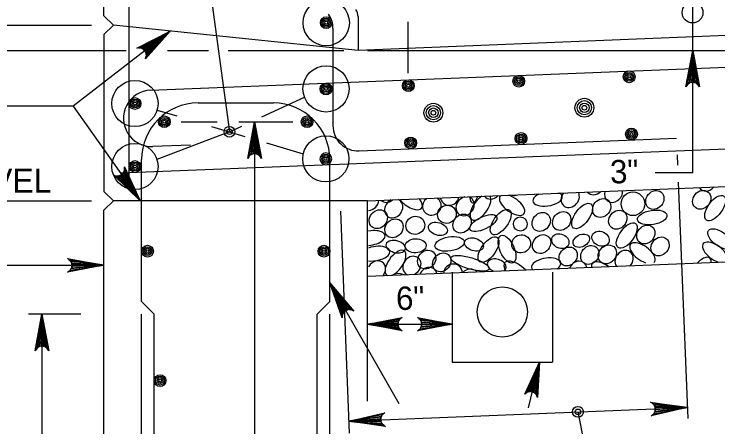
# Model space of a CAD drawing. Extents: x 638167 to 640248, y 296544 to 298920.
# Drawn here: x 639551.3 to 639646.3, y 298721.8 to 298777.5 of the extents above; entities that cross this region are included whole.
import ezdxf

# ---------------------------------------------------------------- set-up
doc = ezdxf.new("R2010")
doc.units = 0
for name, color, linetype in [('1', 7, 'Continuous'), ('50', 7, 'Continuous'), ('57', 7, 'Continuous')]:
    doc.layers.add(name, color=color, linetype=linetype)

# ---------------------------------------------------------------- blocks, each defined once
blk = doc.blocks.new('DIMDOT')
at = {"layer": '57'}
for radius in [2, 1]:
    blk.add_circle((0, 0), radius, dxfattribs=at)
blk = doc.blocks.new('BAR')
at = {"layer": '50'}
for radius in [2, 1.5, 1, 0.5]:
    blk.add_circle((0, 0), radius, dxfattribs=at)

msp = doc.modelspace()

# ---------------------------------------------------------------- linework, layer by layer
at = {"layer": '1'}
for p, q in [((639642.927, 298756.115), (639642.927, 298843.716)), ((639563.476, 298777.252), (639563.476, 298842.446)), ((639566.863, 298754.839), (639566.863, 298793.251)), ((639576.379, 298790.972), (639580.411, 298761.612)), ((639792.111, 298780.369), (639597.766, 298772.596)), ((639563.476, 298777.252), (639564.746, 298775.982)), ((639597.766, 298777.144), (639597.766, 298772.596)), ((639604.54, 298769.508), (639604.54, 298776.442)), ((639494.683, 298775.982), (639561.795, 298775.982)), ((639563.476, 298774.712), (639564.746, 298775.982)), ((639597.766, 298772.596), (639564.746, 298775.982)), ((639594.38, 298775.549), (639594.38, 298762.427)), ((639572.395, 298775.198), (639559.324, 298765.07)), ((639563.476, 298774.712), (639563.476, 298753.58)), ((639569.769, 298767.239), (639757.112, 298774.733)), ((639500.606, 298772.596), (639566.491, 298772.596)), ((639572.037, 298772.596), (639577.584, 298772.596)), ((639580.232, 298772.596), (639595.848, 298772.596)), ((639599.028, 298772.596), (639657.756, 298772.596)), ((639584.794, 298763.647), (639590.514, 298766.303)), ((639559.324, 298765.07), (639526.988, 298765.07)), ((639559.324, 298765.07), (639568.341, 298752.31)), ((639576.176, 298765.496), (639586.334, 298765.496)), ((639570.649, 298764.544), (639573.311, 298763.744)), ((639565.771, 298756.064), (639757.552, 298763.735)), ((639573.907, 298762.964), (639578.756, 298762.964)), ((639581.684, 298762.964), (639588.943, 298762.964)), ((639583.796, 298762.964), (639583.796, 298658.271)), ((639577.973, 298762.344), (639582.464, 298760.995)), ((639580.411, 298761.612), (639582.067, 298762.38)), ((639580.411, 298761.612), (639570.625, 298757.891)), ((639585.403, 298760.113), (639590.367, 298758.622)), ((639597.902, 298759.043), (639640.737, 298760.757)), ((639575.149, 298759.828), (639570.073, 298759.625)), ((639599.034, 298752.31), (639792.923, 298760.066)), ((639640.827, 298758.506), (639640.883, 298757.124)), ((639568.556, 298738.713), (639568.556, 298757.876)), ((639593.954, 298738.713), (639593.954, 298757.876)), ((639637.869, 298756.115), (639642.927, 298756.115)), ((639640.974, 298754.835), (639642.25, 298722.941)), ((639563.476, 298753.58), (639564.746, 298752.31)), ((639538.025, 298752.31), (639561.795, 298752.31)), ((639564.746, 298752.31), (639563.476, 298751.04)), ((639599.034, 298752.31), (639564.746, 298752.31)), ((639599.034, 298725.289), (639599.034, 298752.31)), ((639563.476, 298650.659), (639563.476, 298751.04)), ((639595.375, 298750.89), (639596.571, 298720.998)), ((639599.034, 298742.142), (639793.329, 298749.914)), ((639522.836, 298743.612), (639563.476, 298743.612)), ((639610.464, 298742.701), (639610.464, 298730.555)), ((639623.997, 298742.701), (639623.997, 298730.555)), ((639593.954, 298741.256), (639603.278, 298724.969)), ((639570.25, 298737.019), (639568.556, 298738.713)), ((639592.261, 298737.019), (639593.954, 298738.713)), ((639560.343, 298737.019), (639553.302, 298737.019)), ((639555.101, 298737.019), (639555.101, 298686.219)), ((639568.556, 298663.359), (639568.556, 298737.019)), ((639570.25, 298686.219), (639570.25, 298737.019)), ((639592.261, 298686.219), (639592.261, 298737.019)), ((639593.954, 298663.359), (639593.954, 298737.019)), ((639599.034, 298735.675), (639610.464, 298735.675)), ((639610.464, 298730.555), (639623.997, 298730.555)), ((639620.755, 298724.374), (639622.255, 298730.555)), ((639596.506, 298722.616), (639642.19, 298724.443)), ((639627.44, 298723.853), (639628.333, 298719.377))]:
    msp.add_line(p, q, dxfattribs=at)
for points in [[(639572.395, 298775.198), (639569.062, 298771.446), (639569.132, 298771.666), (639569.201, 298771.886), (639569.178, 298772.077), (639569.154, 298772.268), (639569.075, 298772.416), (639568.996, 298772.564), (639568.872, 298772.678), (639568.749, 298772.791), (639568.57, 298772.862), (639568.391, 298772.932), (639568.16, 298772.92), (639567.929, 298772.908), (639572.395, 298775.198), (639568.16, 298772.92), (639568.391, 298772.932), (639572.395, 298775.198), (639568.57, 298772.862), (639568.749, 298772.791), (639572.395, 298775.198), (639568.872, 298772.678), (639568.996, 298772.564), (639572.395, 298775.198), (639569.075, 298772.416), (639569.154, 298772.268), (639572.395, 298775.198), (639569.178, 298772.077), (639569.201, 298771.886), (639572.395, 298775.198), (639569.132, 298771.666)], [(639642.927, 298772.596), (639643.852, 298767.663), (639643.72, 298767.853), (639643.588, 298768.043), (639643.423, 298768.141), (639643.258, 298768.239), (639643.092, 298768.267), (639642.927, 298768.296), (639642.761, 298768.267), (639642.596, 298768.239), (639642.431, 298768.141), (639642.265, 298768.043), (639642.134, 298767.853), (639642.002, 298767.663), (639642.927, 298772.596), (639642.134, 298767.853), (639642.265, 298768.043), (639642.927, 298772.596), (639642.431, 298768.141), (639642.596, 298768.239), (639642.927, 298772.596), (639642.761, 298768.267), (639642.927, 298768.296), (639642.927, 298772.596), (639643.092, 298768.267), (639643.258, 298768.239), (639642.927, 298772.596), (639643.423, 298768.141), (639643.588, 298768.043), (639642.927, 298772.596), (639643.72, 298767.853)], [(639583.796, 298762.964), (639584.721, 298758.031), (639584.59, 298758.221), (639584.458, 298758.411), (639584.293, 298758.509), (639584.127, 298758.607), (639583.962, 298758.635), (639583.796, 298758.664), (639583.631, 298758.635), (639583.466, 298758.607), (639583.3, 298758.509), (639583.135, 298758.411), (639583.003, 298758.221), (639582.872, 298758.031), (639583.796, 298762.964), (639583.003, 298758.221), (639583.135, 298758.411), (639583.796, 298762.964), (639583.3, 298758.509), (639583.466, 298758.607), (639583.796, 298762.964), (639583.631, 298758.635), (639583.796, 298758.664), (639583.796, 298762.964), (639583.962, 298758.635), (639584.127, 298758.607), (639583.796, 298762.964), (639584.293, 298758.509), (639584.458, 298758.411), (639583.796, 298762.964), (639584.59, 298758.221)], [(639568.341, 298752.31), (639564.739, 298755.805), (639564.956, 298755.725), (639565.173, 298755.646), (639565.365, 298755.662), (639565.557, 298755.677), (639565.708, 298755.749), (639565.859, 298755.822), (639565.978, 298755.94), (639566.097, 298756.059), (639566.175, 298756.234), (639566.254, 298756.41), (639566.252, 298756.641), (639566.25, 298756.872), (639568.341, 298752.31), (639566.252, 298756.641), (639566.254, 298756.41), (639568.341, 298752.31), (639566.175, 298756.234), (639566.097, 298756.059), (639568.341, 298752.31), (639565.978, 298755.94), (639565.859, 298755.822), (639568.341, 298752.31), (639565.708, 298755.749), (639565.557, 298755.677), (639568.341, 298752.31), (639565.365, 298755.662), (639565.173, 298755.646), (639568.341, 298752.31), (639564.956, 298755.725)], [(639563.476, 298743.612), (639558.544, 298742.687), (639558.734, 298742.819), (639558.924, 298742.951), (639559.022, 298743.116), (639559.12, 298743.281), (639559.148, 298743.447), (639559.177, 298743.612), (639559.148, 298743.778), (639559.12, 298743.943), (639559.022, 298744.108), (639558.924, 298744.274), (639558.734, 298744.405), (639558.544, 298744.537), (639563.476, 298743.612), (639558.734, 298744.405), (639558.924, 298744.274), (639563.476, 298743.612), (639559.022, 298744.108), (639559.12, 298743.943), (639563.476, 298743.612), (639559.148, 298743.778), (639559.177, 298743.612), (639563.476, 298743.612), (639559.148, 298743.447), (639559.12, 298743.281), (639563.476, 298743.612), (639559.022, 298743.116), (639558.924, 298742.951), (639563.476, 298743.612), (639558.734, 298742.819)], [(639593.954, 298741.256), (639597.207, 298737.434), (639596.998, 298737.534), (639596.79, 298737.633), (639596.598, 298737.636), (639596.405, 298737.639), (639596.248, 298737.582), (639596.09, 298737.524), (639595.961, 298737.417), (639595.831, 298737.31), (639595.736, 298737.143), (639595.642, 298736.976), (639595.622, 298736.746), (639595.602, 298736.515), (639593.954, 298741.256), (639595.622, 298736.746), (639595.642, 298736.976), (639593.954, 298741.256), (639595.736, 298737.143), (639595.831, 298737.31), (639593.954, 298741.256), (639595.961, 298737.417), (639596.09, 298737.524), (639593.954, 298741.256), (639596.248, 298737.582), (639596.405, 298737.639), (639593.954, 298741.256), (639596.598, 298737.636), (639596.79, 298737.633), (639593.954, 298741.256), (639596.998, 298737.534)], [(639555.101, 298737.019), (639556.026, 298732.087), (639555.895, 298732.277), (639555.763, 298732.467), (639555.598, 298732.565), (639555.432, 298732.663), (639555.267, 298732.691), (639555.101, 298732.72), (639554.936, 298732.691), (639554.771, 298732.663), (639554.605, 298732.565), (639554.44, 298732.467), (639554.308, 298732.277), (639554.177, 298732.087), (639555.101, 298737.019), (639554.308, 298732.277), (639554.44, 298732.467), (639555.101, 298737.019), (639554.605, 298732.565), (639554.771, 298732.663), (639555.101, 298737.019), (639554.936, 298732.691), (639555.101, 298732.72), (639555.101, 298737.019), (639555.267, 298732.691), (639555.432, 298732.663), (639555.101, 298737.019), (639555.598, 298732.565), (639555.763, 298732.467), (639555.101, 298737.019), (639555.895, 298732.277)], [(639599.034, 298735.675), (639603.732, 298736.556), (639603.551, 298736.431), (639603.37, 298736.305), (639603.276, 298736.148), (639603.183, 298735.99), (639603.156, 298735.833), (639603.129, 298735.675), (639603.156, 298735.518), (639603.183, 298735.36), (639603.276, 298735.203), (639603.37, 298735.045), (639603.551, 298734.92), (639603.732, 298734.794), (639599.034, 298735.675), (639603.551, 298734.92), (639603.37, 298735.045), (639599.034, 298735.675), (639603.276, 298735.203), (639603.183, 298735.36), (639599.034, 298735.675), (639603.156, 298735.518), (639603.129, 298735.675), (639599.034, 298735.675), (639603.156, 298735.833), (639603.183, 298735.99), (639599.034, 298735.675), (639603.276, 298736.148), (639603.37, 298736.305), (639599.034, 298735.675), (639603.551, 298736.431)], [(639610.464, 298735.675), (639605.766, 298734.794), (639605.947, 298734.92), (639606.128, 298735.045), (639606.222, 298735.203), (639606.315, 298735.36), (639606.342, 298735.518), (639606.369, 298735.675), (639606.342, 298735.833), (639606.315, 298735.99), (639606.222, 298736.148), (639606.128, 298736.305), (639605.947, 298736.431), (639605.766, 298736.556), (639610.464, 298735.675), (639605.947, 298736.431), (639606.128, 298736.305), (639610.464, 298735.675), (639606.222, 298736.148), (639606.315, 298735.99), (639610.464, 298735.675), (639606.342, 298735.833), (639606.369, 298735.675), (639610.464, 298735.675), (639606.342, 298735.518), (639606.315, 298735.36), (639610.464, 298735.675), (639606.222, 298735.203), (639606.128, 298735.045), (639610.464, 298735.675), (639605.947, 298734.92)], [(639622.255, 298730.555), (639621.965, 298725.784), (639621.887, 298725.99), (639621.81, 298726.196), (639621.68, 298726.325), (639621.55, 298726.454), (639621.404, 298726.519), (639621.257, 298726.583), (639621.098, 298726.595), (639620.939, 298726.608), (639620.763, 298726.555), (639620.588, 298726.503), (639620.422, 298726.358), (639620.256, 298726.213), (639622.255, 298730.555), (639620.422, 298726.358), (639620.588, 298726.503), (639622.255, 298730.555), (639620.763, 298726.555), (639620.939, 298726.608), (639622.255, 298730.555), (639621.098, 298726.595), (639621.257, 298726.583), (639622.255, 298730.555), (639621.404, 298726.519), (639621.55, 298726.454), (639622.255, 298730.555), (639621.68, 298726.325), (639621.81, 298726.196), (639622.255, 298730.555), (639621.887, 298725.99)], [(639642.19, 298724.443), (639637.298, 298723.322), (639637.483, 298723.461), (639637.667, 298723.6), (639637.759, 298723.769), (639637.85, 298723.938), (639637.872, 298724.105), (639637.894, 298724.271), (639637.859, 298724.435), (639637.824, 298724.599), (639637.719, 298724.761), (639637.615, 298724.922), (639637.419, 298725.046), (639637.224, 298725.17), (639642.19, 298724.443), (639637.419, 298725.046), (639637.615, 298724.922), (639642.19, 298724.443), (639637.719, 298724.761), (639637.824, 298724.599), (639642.19, 298724.443), (639637.859, 298724.435), (639637.894, 298724.271), (639642.19, 298724.443), (639637.872, 298724.105), (639637.85, 298723.938), (639642.19, 298724.443), (639637.759, 298723.769), (639637.667, 298723.6), (639642.19, 298724.443), (639637.483, 298723.461)], [(639596.506, 298722.616), (639601.398, 298723.737), (639601.213, 298723.598), (639601.029, 298723.459), (639600.937, 298723.289), (639600.846, 298723.12), (639600.824, 298722.954), (639600.803, 298722.788), (639600.838, 298722.623), (639600.873, 298722.459), (639600.977, 298722.298), (639601.082, 298722.137), (639601.277, 298722.013), (639601.472, 298721.889), (639596.506, 298722.616), (639601.277, 298722.013), (639601.082, 298722.137), (639596.506, 298722.616), (639600.977, 298722.298), (639600.873, 298722.459), (639596.506, 298722.616), (639600.838, 298722.623), (639600.803, 298722.788), (639596.506, 298722.616), (639600.824, 298722.954), (639600.846, 298723.12), (639596.506, 298722.616), (639600.937, 298723.289), (639601.029, 298723.459), (639596.506, 298722.616), (639601.213, 298723.598)]]:
    msp.add_lwpolyline(points, dxfattribs=at)
for centre, radius in [((639593.467, 298776.326), 3.119), ((639642.901, 298777.689), 1.404), ((639593.438, 298767.391), 3.119), ((639567.656, 298765.424), 3.119), ((639593.417, 298757.964), 3.119), ((639567.656, 298756.933), 3.119), ((639634.861, 298751.909), 1.595), ((639617.23, 298737.321), 3.383)]:
    msp.add_circle(centre, radius, dxfattribs=at)
for centre, radius, start, end in [((639590.993, 298775.549), 3.387, 360, 34.85446), ((639596.073, 298777.144), 1.693, 0, 34.85446), ((639569.921, 298763.432), 3.81, 92.29061, 272.29061), ((639576.176, 298757.876), 7.62, 90, 180), ((639586.334, 298757.876), 7.62, 0, 90), ((639597.766, 298762.427), 3.387, 180, 272.29061)]:
    msp.add_arc(centre, radius, start, end, dxfattribs=at)
for centre, major_axis, ratio, start_param, end_param in [((639629.72, 298754.393), (0.86, 1.048), 0.844245, 2.967408, 4.603431), ((639632.24, 298753.367), (0.86, 1.048), 0.844245, 2.008108, 5.562731), ((639644.894, 298754.888), (0.86, 1.048), 0.844245, 2.840874, 4.729965), ((639604.734, 298752.513), (-1.624, 1.174), 0.479042, 1.014341, 4.173787), ((639607.722, 298751.6), (-1.167, -0.522), 0.948581, 4.858014, 10.05193), ((639610.116, 298752.933), (-1.167, -0.522), 0.948581, 6.041055, 8.868889), ((639612.209, 298751.575), (0.86, 1.048), 0.844245, 0.812597, 6.758242), ((639614.282, 298751.415), (-1.174, -1.624), 0.479042, 3.984367, 9.301958), ((639613.542, 298754.709), (0.301, 2.685), 0.282192, 2.36721, 4.002176), ((639615.837, 298753.809), (0.86, 1.048), 0.844245, 2.937326, 4.633513), ((639618.551, 298751.747), (-1.624, 1.174), 0.479042, 6.144575, 11.609923), ((639619.093, 298754.301), (0.86, 1.048), 0.844245, 3.456732, 4.114107), ((639623.342, 298752.581), (-1.979, -0.318), 0.479042, 5.260141, 9.956857), ((639622.836, 298754.923), (-1.174, -1.624), 0.479042, 0.238343, 0.481611), ((639625.017, 298754.59), (0.86, 1.048), 0.844245, 3.627473, 3.943366), ((639626.396, 298752.682), (0.86, 1.048), 0.844245, 1.619643, 5.951196), ((639599.332, 298752.275), (0.86, 1.048), 0.844245, 3.791699, 5.383667), ((639601.748, 298753.372), (0.86, 1.048), 0.844245, 3.07937, 4.491469), ((639602.569, 298751.281), (0.86, 1.048), 0.844245, 1.061779, 6.50906), ((639599.433, 298747.294), (-1.979, -0.318), 0.479042, 1.367878, 4.761562), ((639600.069, 298745.184), (-1.979, -0.318), 0.479042, 1.031728, 5.097712), ((639636.142, 298745.255), (-1.624, 1.174), 0.479042, 3.037298, 8.434015), ((639645.954, 298745.33), (-1.624, 1.174), 0.479042, 3.037298, 8.434015), ((639602.819, 298743.913), (-1.174, -1.624), 0.479042, 0.613344, 6.389796), ((639633.669, 298744.343), (0.86, 1.048), 0.844245, 4.644979, 9.209045), ((639600.251, 298742.932), (0.86, 1.048), 0.844245, 4.720434, 8.098528), ((639605.029, 298743.556), (0.86, 1.048), 0.844245, 4.147339, 9.706685), ((639616.476, 298743.572), (1.251, -0.386), 0.646802, 5.825434, 10.881517), ((639619.159, 298742.761), (-1.624, 1.174), 0.479042, 4.285286, 7.186027), ((639623.152, 298743.605), (-1.979, -0.318), 0.479042, 2.351329, 6.582484), ((639627.417, 298742.905), (0.86, 1.048), 0.844245, 5.644884, 8.209141), ((639630.962, 298742.677), (-1.624, 1.174), 0.479042, 4.69169, 6.779622), ((639644.025, 298742.979), (-1.174, -1.624), 0.479042, 2.538262, 4.464878), ((639607.195, 298742.058), (0.86, 1.048), 0.844245, 5.676034, 8.17799), ((639610.572, 298742.56), (-1.167, -0.522), 0.948581, 2.768835, 5.857924), ((639612.857, 298741.875), (-1.167, -0.522), 0.948581, 3.464469, 5.16229), ((639605.03, 298741.117), (2.42, -1.201), 0.282192, 2.12602, 3.204967)]:
    msp.add_ellipse(centre, major_axis=major_axis, ratio=ratio, start_param=start_param, end_param=end_param, dxfattribs=at)
for centre, major_axis, ratio in [((639637.815, 298752.421), (0.86, 1.048), 0.844245), ((639644.144, 298752.443), (0.86, 1.048), 0.844245), ((639630.644, 298751.334), (0.86, 1.048), 0.844245), ((639645.951, 298751.325), (-1.174, -1.624), 0.479042), ((639609.752, 298750.487), (-1.167, -0.522), 0.948581), ((639628.001, 298750.26), (-1.174, -1.624), 0.479042), ((639600.499, 298749.826), (0.86, 1.048), 0.844245), ((639611.799, 298749.238), (0.86, 1.048), 0.844245), ((639617.019, 298749.44), (-1.174, -1.624), 0.479042), ((639622.479, 298749.463), (0.86, 1.048), 0.844245), ((639625.243, 298749.586), (0.86, 1.048), 0.844245), ((639632.815, 298749.753), (0.86, 1.048), 0.844245), ((639637.465, 298750.062), (-1.979, -0.318), 0.479042), ((639602.612, 298748.599), (0.86, 1.048), 0.844245), ((639605.49, 298748.998), (-1.167, -0.522), 0.948581), ((639614.673, 298749.314), (1.803, 0.852), 0.422273), ((639619.664, 298749.177), (-0.038, 0.956), 0.982495), ((639608.537, 298748.519), (1.251, -0.386), 0.646802), ((639634.026, 298747.627), (-1.174, -1.624), 0.479042), ((639636.596, 298747.763), (0.86, 1.048), 0.844245), ((639646.675, 298747.132), (-1.624, 1.174), 0.479042), ((639617.866, 298745.788), (0.82, -1.829), 0.479042), ((639619.77, 298746.507), (-1.167, -0.522), 0.948581), ((639622.531, 298746.476), (0.86, 1.048), 0.844245), ((639625.059, 298746.868), (1.096, -0.509), 0.796199), ((639627.889, 298746.927), (1.058, 0.529), 0.687276), ((639630.489, 298747.199), (1.096, -0.509), 0.796199), ((639602.844, 298746.123), (1.251, -0.386), 0.646802), ((639605.53, 298746.242), (1.409, 0.056), 0.671766), ((639610.124, 298746.495), (-1.979, -0.318), 0.479042), ((639613.409, 298746.425), (1.251, -0.386), 0.646802), ((639615.366, 298745.724), (-1.174, -1.624), 0.479042), ((639638.517, 298746.154), (0.86, 1.048), 0.844245), ((639626.119, 298744.801), (0.86, 1.048), 0.844245), ((639629.041, 298745.005), (0.86, 1.048), 0.844245), ((639631.403, 298745.08), (0.86, 1.048), 0.844245), ((639607.027, 298744.38), (0.86, 1.048), 0.844245), ((639609.059, 298744.003), (0.86, 1.048), 0.844245), ((639612.882, 298743.878), (2.592, -0.763), 0.282192)]:
    msp.add_ellipse(centre, major_axis=major_axis, ratio=ratio, dxfattribs=at)

# ---------------------------------------------------------------- block references
for p, xscale, yscale, rotation in [((639593.467, 298776.326), 0.3968757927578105, 0.39687579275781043, -90.00000000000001), ((639634.353, 298769.028), 0.39687579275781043, 0.3968757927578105, -82.05765865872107), ((639604.55, 298767.836), 0.39687579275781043, 0.3968757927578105, -82.05765865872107), ((639619.452, 298768.432), 0.39687579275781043, 0.3968757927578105, -82.05765865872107), ((639593.438, 298767.391), 0.39687579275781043, 0.3968757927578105, -82.05765865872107), ((639567.656, 298765.424), 0.39687579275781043, 0.3968757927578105, -82.05765865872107), ((639571.624, 298762.964), 0.3968757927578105, 0.39687579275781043, -90.00000000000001), ((639590.887, 298762.964), 0.3968757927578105, 0.39687579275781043, -90.00000000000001), ((639634.662, 298761.308), 0.39687579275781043, 0.3968757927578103, -87.70938995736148), ((639619.76, 298760.712), 0.39687579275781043, 0.3968757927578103, -87.70938995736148), ((639604.859, 298760.116), 0.39687579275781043, 0.3968757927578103, -87.70938995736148), ((639593.417, 298757.964), 0.39687579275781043, -0.3968757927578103, -87.70938995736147), ((639567.656, 298756.933), 0.39687579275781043, 0.3968757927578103, -87.70938995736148), ((639569.349, 298745.515), 0.3968757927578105, 0.39687579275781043, -90.00000000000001), ((639593.161, 298745.515), 0.3968757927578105, 0.39687579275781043, -90.00000000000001), ((639571.042, 298728.066), 0.3968757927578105, 0.39687579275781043, -90.00000000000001)]:
    msp.add_blockref('BAR', p, dxfattribs=dict(at, xscale=xscale, yscale=yscale, rotation=rotation))
for name, p, xscale, yscale in [('BAR', (639628.304, 298764.859), 0.6349782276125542, 0.6349782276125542), ('BAR', (639607.926, 298764.189), 0.6349782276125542, 0.6349782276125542), ('DIMDOT', (639580.411, 298761.612), 0.3674999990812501, 0.36749999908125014), ('DIMDOT', (639627.44, 298723.853), 0.3674999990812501, 0.36749999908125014)]:
    msp.add_blockref(name, p, dxfattribs=dict(at, xscale=xscale, yscale=yscale))

# ---------------------------------------------------------------- texts
for s, p in [('3"', (639631.81, 298754.633)), ('6"', (639602.928, 298737.563))]:
    msp.add_text(s, height=3.15, rotation=1.54816, dxfattribs=at).set_placement(p)
msp.add_text('LEVEL', height=3.2256, dxfattribs=at).set_placement((639542.96, 298753.425))

doc.saveas('drawing.dxf')
